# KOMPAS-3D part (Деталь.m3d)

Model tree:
1. Эскиз:1
2. Операция выдавливания:1
     Расстояние 1 = 12
3. Эскиз:2
4. Вырезать элемент выдавливания:1
     Расстояние 1 = 12
5. Скругление:1
     Радиус = 6
6. Эскиз:3
7. Вырезать элемент выдавливания:2
     Расстояние 1 = 38
8. Эскиз:4
9. Операция выдавливания:2
     Расстояние 1 = 5
10. Эскиз:5
11. Операция выдавливания:3
     Расстояние 1 = 5; Расстояние 2 = 5
12. Эскиз:6
13. Операция выдавливания:4
     Расстояние 1 = 5; Расстояние 2 = 5
14. Условное изображение резьбы:1
     Длина резьбы = 38; Шаг резьбы = 1; Номинальный диаметр резьбы = 5.08253
15. Линейный размер:10
     Значение = 63
16. Линейный размер:11
     Значение = 38
17. Линейный размер:12
     Значение = 12
18. Линейный размер:13
     Значение = 15
19. Линейный размер:14
     Значение = 13
20. Линейный размер:15
     Значение = 25
21. Линейный размер:16
     Значение = 15
22. Линейный размер:17
     Значение = 20
23. Радиальный размер:4
     Значение = 10
24. Радиальный размер:5
     Значение = 6
25. Эскиз:13
26. Линейный размер:18
     Значение = 5
27. Линейный размер:19
     Значение = 5
28. Эскиз:14
29. Линейный размер:20
     Значение = 4
